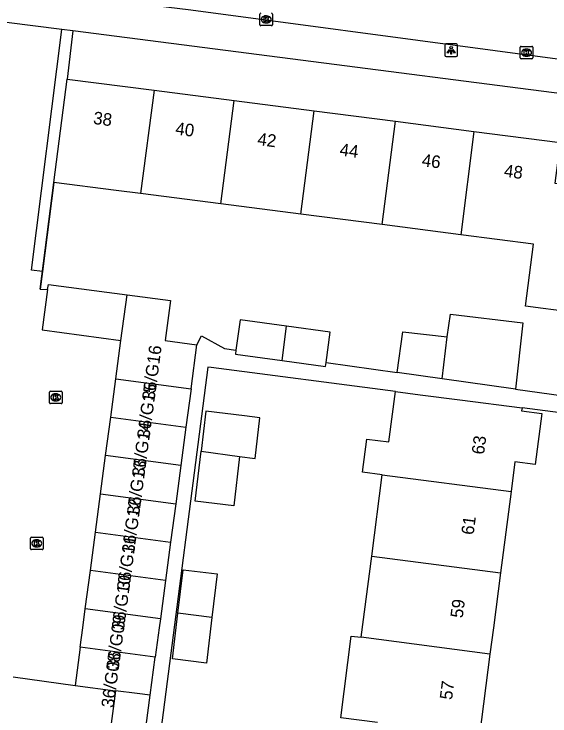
# Model space of a CAD drawing. Extents: x 162186 to 163152, y 385513 to 386513.
# Drawn here: x 162544.8 to 162587.5, y 386243 to 386298.9 of the extents above; entities that cross this region are included whole.
import ezdxf

# ---------------------------------------------------------------- set-up
doc = ezdxf.new("R2010")
doc.units = 0
for name, color, linetype in [('IMGEO_Kolk', 7, 'Continuous'), ('IMGEO_Lichtpunt', 7, 'Continuous'), ('IMGEO_Muur', 7, 'Continuous'), ('IMGEO_Pand', 7, 'Continuous'), ('IMGEO_Pand_nummerreeks', 7, 'Continuous'), ('IMGEO_Rijbaan_lokaal_open', 7, 'Continuous'), ('IMGEO_Voetpad_open', 7, 'Continuous')]:
    doc.layers.add(name, color=color, linetype=linetype)

msp = doc.modelspace()

# ---------------------------------------------------------------- linework, layer by layer
at = {"layer": 'IMGEO_Kolk'}
for p, q in [((162564.419, 386298.039), (162564.419, 386298.891)), ((162564.907, 386298.745), (162564.932, 386298.745)), ((162565.42, 386298.891), (162565.42, 386298.039)), ((162564.93, 386298.185), (162564.905, 386298.185)), ((162565.346, 386297.965), (162564.494, 386297.965)), ((162585.152, 386295.389), (162585.152, 386296.241)), ((162585.227, 386296.315), (162586.079, 386296.315)), ((162585.64, 386296.095), (162585.665, 386296.095)), ((162586.153, 386296.241), (162586.153, 386295.389)), ((162586.079, 386295.315), (162585.227, 386295.315)), ((162585.663, 386295.535), (162585.638, 386295.535)), ((162547.649, 386267.926), (162547.649, 386268.778)), ((162547.724, 386268.852), (162548.576, 386268.852)), ((162548.137, 386268.632), (162548.162, 386268.632)), ((162548.65, 386268.778), (162548.65, 386267.926)), ((162548.16, 386268.072), (162548.135, 386268.072)), ((162548.576, 386267.852), (162547.724, 386267.852)), ((162546.137, 386256.294), (162546.137, 386257.146)), ((162546.212, 386257.22), (162547.064, 386257.22)), ((162546.625, 386257), (162546.65, 386257)), ((162547.138, 386257.146), (162547.138, 386256.294)), ((162547.064, 386256.22), (162546.212, 386256.22)), ((162546.648, 386256.44), (162546.623, 386256.44))]:
    msp.add_line(p, q, dxfattribs=at)
for points in [[(162564.419, 386298.039), (162564.419, 386298.891)], [(162564.74, 386298.665), (162564.863, 386298.665), (162564.863, 386298.514), (162564.993, 386298.665), (162565.157, 386298.665), (162565.011, 386298.514), (162565.164, 386298.265), (162565.012, 386298.265), (162564.927, 386298.429), (162564.863, 386298.362), (162564.863, 386298.265), (162564.74, 386298.265), (162564.74, 386298.665)], [(162565.42, 386298.891), (162565.42, 386298.039)], [(162565.346, 386297.965), (162564.494, 386297.965)], [(162585.152, 386295.389), (162585.152, 386296.241)], [(162585.227, 386296.315), (162586.079, 386296.315)], [(162585.473, 386296.015), (162585.596, 386296.015), (162585.596, 386295.864), (162585.726, 386296.015), (162585.89, 386296.015), (162585.744, 386295.864), (162585.897, 386295.615), (162585.745, 386295.615), (162585.66, 386295.779), (162585.596, 386295.712), (162585.596, 386295.615), (162585.473, 386295.615), (162585.473, 386296.015)], [(162586.153, 386296.241), (162586.153, 386295.389)], [(162586.079, 386295.315), (162585.227, 386295.315)], [(162547.649, 386267.926), (162547.649, 386268.778)], [(162547.724, 386268.852), (162548.576, 386268.852)], [(162547.97, 386268.552), (162548.093, 386268.552), (162548.093, 386268.401), (162548.223, 386268.552), (162548.387, 386268.552), (162548.241, 386268.401), (162548.394, 386268.152), (162548.242, 386268.152), (162548.157, 386268.316), (162548.093, 386268.249), (162548.093, 386268.152), (162547.97, 386268.152), (162547.97, 386268.552)], [(162548.65, 386268.778), (162548.65, 386267.926)], [(162548.576, 386267.852), (162547.724, 386267.852)], [(162546.137, 386256.294), (162546.137, 386257.146)], [(162546.212, 386257.22), (162547.064, 386257.22)], [(162546.458, 386256.92), (162546.581, 386256.92), (162546.581, 386256.769), (162546.711, 386256.92), (162546.875, 386256.92), (162546.729, 386256.769), (162546.882, 386256.52), (162546.73, 386256.52), (162546.645, 386256.684), (162546.581, 386256.617), (162546.581, 386256.52), (162546.458, 386256.52), (162546.458, 386256.92)], [(162547.138, 386257.146), (162547.138, 386256.294)], [(162547.064, 386256.22), (162546.212, 386256.22)]]:
    msp.add_lwpolyline(points, dxfattribs=at)
for centre, start, end in [((162564.496, 386298.889), 91.552, 178.448), ((162564.496, 386298.889), 91.552, 178.448), ((162565.344, 386298.889), 1.552, 88.448), ((162565.344, 386298.889), 1.552, 88.448), ((162564.496, 386298.041), 181.552, 268.448), ((162564.496, 386298.041), 181.552, 268.448), ((162565.344, 386298.041), 271.552, 358.448), ((162565.344, 386298.041), 271.552, 358.448), ((162585.229, 386296.239), 91.552, 178.448), ((162585.229, 386296.239), 91.552, 178.448), ((162586.077, 386296.239), 1.552, 88.448), ((162586.077, 386296.239), 1.552, 88.448), ((162585.229, 386295.391), 181.552, 268.448), ((162585.229, 386295.391), 181.552, 268.448), ((162586.077, 386295.391), 271.552, 358.448), ((162586.077, 386295.391), 271.552, 358.448), ((162547.726, 386268.776), 91.552, 178.448), ((162547.726, 386268.776), 91.552, 178.448), ((162548.574, 386268.776), 1.552, 88.448), ((162548.574, 386268.776), 1.552, 88.448), ((162547.726, 386267.928), 181.552, 268.448), ((162547.726, 386267.928), 181.552, 268.448), ((162548.574, 386267.928), 271.552, 358.448), ((162548.574, 386267.928), 271.552, 358.448), ((162546.214, 386257.144), 91.552, 178.448), ((162546.214, 386257.144), 91.552, 178.448), ((162547.062, 386257.144), 1.552, 88.448), ((162547.062, 386257.144), 1.552, 88.448), ((162546.214, 386256.296), 181.552, 268.448), ((162546.214, 386256.296), 181.552, 268.448), ((162547.062, 386256.296), 271.552, 358.448), ((162547.062, 386256.296), 271.552, 358.448)]:
    msp.add_arc(centre, 0.0765, start, end, dxfattribs=at)
for centre, major_axis, ratio, start_param, end_param in [((162564.906, 386298.465), (-0.387, 0.002), 0.722429, 4.712389, 7.853982), ((162564.931, 386298.465), (-0.39, 0.002), 0.717154, 1.570796, 4.712389), ((162585.639, 386295.815), (-0.387, 0.002), 0.722429, 4.712389, 7.853982), ((162585.664, 386295.815), (-0.39, 0.002), 0.717154, 1.570796, 4.712389), ((162548.136, 386268.352), (-0.387, 0.002), 0.722429, 4.712389, 7.853982), ((162548.161, 386268.352), (-0.39, 0.002), 0.717154, 1.570796, 4.712389), ((162546.624, 386256.72), (-0.387, 0.002), 0.722429, 4.712389, 7.853982), ((162546.649, 386256.72), (-0.39, 0.002), 0.717154, 1.570796, 4.712389)]:
    msp.add_ellipse(centre, major_axis=major_axis, ratio=ratio, start_param=start_param, end_param=end_param, dxfattribs=at)
at = {"layer": 'IMGEO_Lichtpunt'}
for p, q in [((162579.152, 386296.41), (162579.152, 386295.603)), ((162579.152, 386296.41), (162579.152, 386295.603)), ((162580.054, 386296.505), (162579.246, 386296.505)), ((162580.054, 386296.505), (162579.246, 386296.505)), ((162580.148, 386295.603), (162580.148, 386296.41)), ((162580.148, 386295.603), (162580.148, 386296.41)), ((162579.246, 386295.509), (162580.054, 386295.509)), ((162579.246, 386295.509), (162580.054, 386295.509))]:
    msp.add_line(p, q, dxfattribs=at)
for points in [[(162579.526, 386296.074), (162579.565, 386296.046), (162579.377, 386295.784), (162579.339, 386295.811), (162579.526, 386296.074)], [(162579.628, 386296.026), (162579.675, 386296.026), (162579.675, 386295.704), (162579.628, 386295.704), (162579.628, 386296.026)], [(162579.738, 386296.046), (162579.776, 386296.073), (162579.963, 386295.811), (162579.924, 386295.783), (162579.738, 386296.046)]]:
    msp.add_lwpolyline(points, dxfattribs=at)
msp.add_circle((162579.651, 386296.208), 0.0994, dxfattribs=at)
for centre, start, end in [((162579.246, 386296.41), 90, 180), ((162579.246, 386296.41), 90, 180), ((162580.054, 386296.41), 0, 90), ((162580.054, 386296.41), 0, 90), ((162579.246, 386295.603), 180, 270), ((162579.246, 386295.603), 180, 270), ((162580.054, 386295.603), 270, 0), ((162580.054, 386295.603), 270, 360)]:
    msp.add_arc(centre, 0.0946, start, end, dxfattribs=at)
at = {"layer": 'IMGEO_Muur'}
for points in [[(162546.919, 386276.982), (162547.998, 386285.478)], [(162544.758, 386246.095), (162549.689, 386245.409)]]:
    msp.add_lwpolyline(points, dxfattribs=at)
at = {"layer": 'IMGEO_Pand'}
for points in [[(162547.998, 386285.478), (162549.057, 386293.711)], [(162549.057, 386293.711), (162555.998, 386292.818)], [(162555.998, 386292.818), (162554.903, 386284.59)], [(162555.998, 386292.818), (162562.354, 386292.001)], [(162561.298, 386283.768), (162562.354, 386292.001)], [(162562.354, 386292.001), (162568.736, 386291.18)], [(162567.681, 386282.947), (162568.736, 386291.18)], [(162568.736, 386291.18), (162575.215, 386290.347)], [(162574.16, 386282.114), (162575.215, 386290.347)], [(162575.215, 386290.347), (162581.461, 386289.543)], [(162581.461, 386289.543), (162588.321, 386288.661), (162587.903, 386285.409), (162593.206, 386284.727), (162591.927, 386274.787), (162586.968, 386275.425), (162585.56, 386275.606), (162586.198, 386280.566), (162580.406, 386281.311)], [(162581.461, 386289.543), (162580.406, 386281.311)], [(162554.903, 386284.59), (162552.958, 386284.84), (162547.998, 386285.478)], [(162561.298, 386283.768), (162554.903, 386284.59)], [(162567.681, 386282.947), (162561.298, 386283.768)], [(162574.16, 386282.114), (162567.681, 386282.947)], [(162580.406, 386281.311), (162574.16, 386282.114)], [(162547.506, 386276.942), (162547.08, 386273.739), (162553.345, 386272.876)], [(162547.506, 386276.942), (162547.561, 386277.357), (162553.83, 386276.524)], [(162553.345, 386272.876), (162553.83, 386276.524)], [(162553.83, 386276.524), (162557.287, 386276.064), (162557.234, 386275.665), (162556.862, 386272.872), (162559.392, 386272.535)], [(162579.325, 386273.17), (162579.595, 386274.986), (162585.369, 386274.278), (162584.764, 386269.01)], [(162566.537, 386274.02), (162562.835, 386274.525), (162562.507, 386272.118)], [(162566.187, 386271.293), (162566.537, 386274.02)], [(162569.68, 386271.143), (162570.008, 386273.546), (162566.537, 386274.02)], [(162575.348, 386270.32), (162575.784, 386273.57), (162579.325, 386273.17)], [(162578.933, 386269.821), (162579.325, 386273.17)], [(162552.939, 386269.824), (162553.345, 386272.876)], [(162558.925, 386269.027), (162559.392, 386272.535)], [(162562.507, 386272.118), (162562.464, 386271.801), (162566.187, 386271.293)], [(162566.187, 386271.293), (162569.636, 386270.822), (162569.68, 386271.143)], [(162578.933, 386269.821), (162575.348, 386270.32)], [(162552.533, 386266.772), (162552.939, 386269.824)], [(162552.939, 386269.824), (162558.925, 386269.027)], [(162584.764, 386269.01), (162578.933, 386269.821)], [(162558.925, 386269.027), (162558.519, 386265.975)], [(162574.163, 386262.176), (162572.592, 386262.381), (162572.936, 386265.028), (162574.686, 386264.8), (162575.21, 386268.822)], [(162575.21, 386268.822), (162577.184, 386268.565), (162580.333, 386268.155), (162585.291, 386267.509)], [(162585.291, 386267.509), (162585.26, 386267.268), (162586.863, 386267.059), (162586.335, 386263.008), (162584.731, 386263.217), (162584.422, 386260.842)], [(162552.126, 386263.72), (162552.533, 386266.772)], [(162552.533, 386266.772), (162558.519, 386265.975)], [(162562.792, 386263.654), (162564.032, 386263.492), (162564.418, 386266.728), (162563.176, 386266.876), (162560.107, 386267.242), (162559.728, 386264.053)], [(162558.519, 386265.975), (162558.112, 386262.924)], [(162562.792, 386263.654), (162562.323, 386259.712), (162559.254, 386260.077), (162559.728, 386264.053)], [(162559.728, 386264.053), (162562.792, 386263.654)], [(162551.72, 386260.668), (162552.126, 386263.72)], [(162558.112, 386262.924), (162552.126, 386263.72)], [(162558.112, 386262.924), (162557.706, 386259.872)], [(162573.32, 386255.705), (162574.163, 386262.176)], [(162574.163, 386262.176), (162584.422, 386260.842)], [(162551.314, 386257.617), (162551.72, 386260.668)], [(162551.72, 386260.668), (162557.706, 386259.872)], [(162584.422, 386260.842), (162583.579, 386254.371)], [(162557.706, 386259.872), (162557.3, 386256.82)], [(162550.908, 386254.565), (162551.314, 386257.617)], [(162551.314, 386257.617), (162557.3, 386256.82)], [(162557.3, 386256.82), (162556.894, 386253.768)], [(162572.478, 386249.237), (162573.32, 386255.705)], [(162573.32, 386255.705), (162583.579, 386254.371)], [(162550.501, 386251.513), (162550.908, 386254.565)], [(162556.894, 386253.768), (162550.908, 386254.565)], [(162557.876, 386251.158), (162558.288, 386254.613), (162561.01, 386254.288), (162560.594, 386250.802)], [(162583.579, 386254.371), (162583.01, 386250), (162582.737, 386247.901)], [(162556.894, 386253.768), (162556.487, 386250.716)], [(162550.095, 386248.461), (162550.3, 386250), (162550.501, 386251.513)], [(162556.487, 386250.716), (162550.501, 386251.513)], [(162560.594, 386250.802), (162560.162, 386247.188), (162557.441, 386247.512), (162557.876, 386251.158)], [(162560.594, 386250.802), (162557.876, 386251.158)], [(162556.487, 386250.716), (162556.392, 386250), (162556.081, 386247.664)], [(162573.783, 386242.452), (162570.863, 386242.824), (162571.691, 386249.337), (162572.478, 386249.237)], [(162582.737, 386247.901), (162572.478, 386249.237)], [(162550.095, 386248.461), (162549.689, 386245.409)], [(162556.081, 386247.664), (162550.095, 386248.461)], [(162582.737, 386247.901), (162581.894, 386241.43)], [(162555.675, 386244.615), (162556.081, 386247.664)], [(162549.689, 386245.409), (162552.918, 386244.979)], [(162552.918, 386244.979), (162551.821, 386236.74)], [(162555.675, 386244.615), (162554.646, 386244.749), (162552.918, 386244.979)], [(162554.579, 386236.376), (162555.675, 386244.615)]]:
    msp.add_lwpolyline(points, dxfattribs=at)
at = {"layer": 'IMGEO_Rijbaan_lokaal_open'}
for points in [[(162549.973, 386300.35), (162558.903, 386299.215), (162607.392, 386292.738)], [(162548.633, 386297.67), (162544.227, 386298.211)], [(162547.095, 386278.367), (162546.214, 386278.489), (162548.633, 386297.67)], [(162547.095, 386278.367), (162546.919, 386276.982), (162547.506, 386276.942)], [(162544.758, 386246.095), (162549.689, 386245.409)]]:
    msp.add_lwpolyline(points, dxfattribs=at)
at = {"layer": 'IMGEO_Voetpad_open'}
for points in [[(162549.509, 386297.552), (162548.633, 386297.67)], [(162549.509, 386297.552), (162549.057, 386293.711)], [(162605.988, 386290.264), (162549.509, 386297.552)], [(162547.998, 386285.478), (162547.095, 386278.367)], [(162559.392, 386272.535), (162559.751, 386273.245), (162561.589, 386272.244), (162562.507, 386272.118)], [(162575.21, 386268.822), (162560.522, 386270.734), (162560.259, 386270.769), (162556.517, 386241.805)], [(162569.68, 386271.143), (162575.348, 386270.32)], [(162584.764, 386269.01), (162602.352, 386266.564)], [(162601.984, 386265.333), (162585.291, 386267.509)]]:
    msp.add_lwpolyline(points, dxfattribs=at)

# ---------------------------------------------------------------- texts
at = {"layer": 'IMGEO_Pand_nummerreeks'}
for s, rotation, p in [('38', 352.671, (162551.094, 386290.142)), ('40', 352.6711, (162557.638, 386289.3)), ('42', 352.6711, (162564.176, 386288.46)), ('44', 352.671, (162570.723, 386287.618)), ('46', 352.671, (162577.267, 386286.776)), ('48', 352.671, (162583.814, 386285.934)), ('36/G16', 82.42, (162556.016, 386268.083)), ('36/G15', 82.418, (162555.61, 386265.031)), ('36/G14', 82.418, (162555.203, 386261.979)), ('63', 82.5804, (162582.261, 386263.759)), ('36/G13', 82.418, (162554.797, 386258.927)), ('36/G12', 82.418, (162554.39, 386255.869)), ('61', 82.5784, (162581.428, 386257.357)), ('36/G11', 82.418, (162553.999, 386252.933)), ('36/G10', 82.418, (162553.579, 386249.775)), ('59', 82.5784, (162580.564, 386250.731)), ('36/G09', 82.4186, (162553.16, 386246.626)), ('36/G08', 82.42, (162552.755, 386243.58)), ('57', 82.5784, (162579.716, 386244.217))]:
    msp.add_text(s, height=1, rotation=rotation, dxfattribs=at).set_placement(p)

doc.saveas('drawing.dxf')
